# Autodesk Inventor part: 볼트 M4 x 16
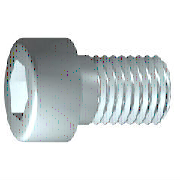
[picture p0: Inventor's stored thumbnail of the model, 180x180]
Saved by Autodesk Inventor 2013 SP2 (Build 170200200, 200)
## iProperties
IsCustomPart: 1
Created: 2012-02
Part Number: 볼트 M4 x 16
Material: 스테인리스강
Description: 6각 소켓 머리 캡 나사
Document SubType Name: Modeling
Standard: ISO 4762
Designer: mduedu
Standard Revision: Fourth edition 2004-03-01
Standards Organization: ISO
Language: ko-KR
Size Designation: M4 x 16
Categories: <MemberInstance><Categories><Category DisplayName="조임쇠" InternalName="e4da775c-781d-43d5-af7c-5136215cf5a6" Mnemonic="FSTN"><Category DisplayName="볼트" InternalN
Density: 8.08 g/cm^3
Author: mduedu
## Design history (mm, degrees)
sketch "스케치1"
  geometry: L1 (-1, 0)-(16, 0); L2 (16, 0)-(16, 2); L3 (16, 2)-(1.75, 2); L4 (1.75, 2)-(1.32, 2); L5 (1.32, 2)-(0, 2); L6 (0, 2)-(0, 3.5); L7 (0, 3.5)-(-4, 3.5); L8 (-4, 3.5)-(-4, 1.732); L9 (-4, 1.732)-(-2, 1.732); L10 (-2, 1.732)-(-1, 0); L11 (-8, 0)-(20, 0) reference; L12 (0, -0.7)-(0, 4.2) reference; L13 (1.75, 2)-(0, 2)
  constraints: 22 end point, 6 parallel, 2 collinear, 2 perpendicular, 1 horizontal, 1 point on line
  dimensions: "d1" = 14.25 distance from line of L3.end L2 (= GEL); "d2" = 0.42952 distance of L4.end L3.end (computed from GAL); "d3" = 4 distance between parallel lines of L8 L6 (= KOH); "d4" = 2 distance of L8.end L9.end (= INTI); "d5" = 60 deg angle of L10 L1; "d6" = 4 diameter of L3 L1 (= GD); "d7" = 4 diameter of L5 L1 (= BDM); "d8" = 3.4641 diameter of L9 L1 (= 1.1547 x SW); "d9" = 7 diameter of L7 L1 (= KOD); "d26" = 16 distance between parallel lines of L12 L2 (= NLG)
revolve "본체" sketch "스케치1" stored, may be unused: angle "d10" = 90 deg
sketch "스케치2"
  geometry: L1 (0, -4.9)-(0, 4.9) reference; L2 (-4.9, 0)-(4.9, 0) reference; L3 (1.732, 0)-(0.866, -1.5); L4 (0.866, -1.5)-(-0.866, -1.5); L5 (-0.866, -1.5)-(-1.732, 0); L6 (-1.732, 0)-(-0.866, 1.5); L7 (-0.866, 1.5)-(0.866, 1.5); L8 (0.866, 1.5)-(1.732, 0); 2 further points
  constraints: 12 end point, 1 coincident, 1 horizontal alignment, 1 point on line, 12 other
extrude "슬롯" join sketch "스케치2" stored distance "d11" = 10; taper "d12" = 0 deg
workplane "Work Plane1"
fillet "Fillet2" dims "d30" = 0.1 (= R)
body "Solid1"
fillet "모깎기1" dims "d17" = 0.4 (= RR)
feature "스레드" dims "d13" = 14.25 (= GEL), "d14" = 0
chamfer "모따기1" distance "d15" = 0.42941 (= -0.5 x SPD + 0.5 x GD); stored, may be unused: second distance "d16" = 0.42941 (= GUL), angle "d27" = 45 deg
other parameters: "GD" = 4 [user parameter; used in 2 equation terms], "NLG" = 16 [user parameter; used in 1 equation term], "GEL" = 14.25 [user parameter; used in 2 equation terms], "KOD" = 7 [user parameter; used in 1 equation term], "KOH" = 4 [user parameter; used in 1 equation term], "INTI" = 2 [user parameter; used in 1 equation term], "GAL" = 0.42941 (= 0.61345 x PTC) [user parameter; used in 1 equation term], "GUL" = 0.42941 (= 0.61345 x PTC) [user parameter; used in 1 equation term], "BDM" = 4 (= NND) [user parameter; used in 1 equation term], "SW" = 3 [user parameter; used in 2 equation terms], "RR" = 0.4 [user parameter; used in 1 equation term], "SPD" = 3.14117 (= NND - 1.2269 x PTC) [user parameter; used in 1 equation term], "d19" = 0, "d28" = 0, "d29" = 0, "R" = 0.1 [user parameter; used in 1 equation term], "TOA" = 30 deg [user parameter], "GD1" = 3.14117 (= THREADDIA - 1.2269 x PTC) [user parameter], "THREADDIA" = 4 [user parameter; used in 1 equation term], "FAWI" = 45 deg [user parameter], "TPU" = 14.28571 (computed from PTC) [user parameter], "PTC" = 0.7 [user parameter; used in 5 equation terms], "NND" = 4 [user parameter; used in 2 equation terms], "E0" = 3.465 (= 1.155 x SW) [user parameter]
